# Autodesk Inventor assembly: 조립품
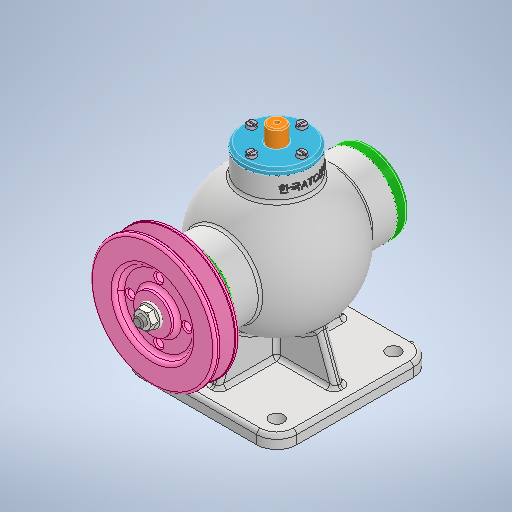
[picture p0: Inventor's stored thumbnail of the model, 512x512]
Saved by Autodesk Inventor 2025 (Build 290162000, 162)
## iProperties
Created: 2024-07
Part Number: 조립품
Document SubType Name: Assembly
Designer: onair
Author: onair
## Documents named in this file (15)
- C:\Users\onair\OneDrive\Desktop\740708V1004\조립품.iam
- C:\Users\onair\OneDrive\Desktop\740708V1004\본체.ipt
- C:\Users\onair\OneDrive\Desktop\740708V1004\V-벨트풀리\V-벨트풀리.ipt
- C:\Users\onair\OneDrive\Desktop\740708V1004\너트 M8\너트 M8.ipt
- C:\Users\onair\OneDrive\Desktop\740708V1004\뒤커버\뒤커버.ipt
- C:\Users\onair\OneDrive\Desktop\740708V1004\베어링- 6202\베어링- 6202.ipt
- C:\Users\onair\OneDrive\Desktop\740708V1004\볼트 M4 x 12\볼트 M4 x 12.ipt
- C:\Users\onair\OneDrive\Desktop\740708V1004\볼트 M4 x 16\볼트 M4 x 16.ipt
- C:\Users\onair\OneDrive\Desktop\740708V1004\상부커버\상부커버.ipt
- C:\Users\onair\OneDrive\Desktop\740708V1004\슬라이드\슬라이드.ipt
- C:\Users\onair\OneDrive\Desktop\740708V1004\앞커버\앞커버.ipt
- C:\Users\onair\OneDrive\Desktop\740708V1004\오일실 15 30 7\오일실 15 30 7.ipt
- C:\Users\onair\OneDrive\Desktop\740708V1004\칼라\칼라.ipt
- C:\Users\onair\OneDrive\Desktop\740708V1004\키 4 x 4 x 12\키 4 x 4 x 12.ipt
- C:\Users\onair\OneDrive\Desktop\740708V1004\편심축\편심축.ipt
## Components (1 placed, 1 different names)
1. V-벨트풀리:1 — 각도:10
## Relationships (1: Angle 1)
- 각도:10 [Angle]: V-벨트풀리:1
